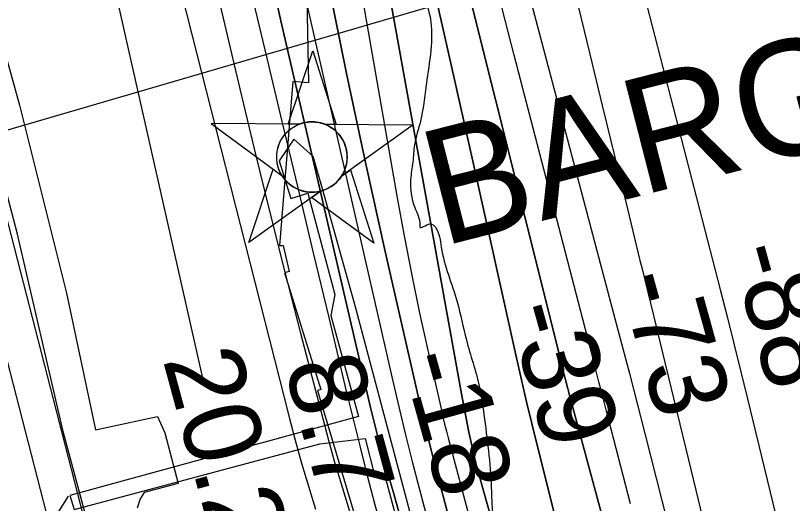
# Model space of a CAD drawing. Extents: x 3405885 to 3443815, y 558517 to 583997.
# Drawn here: x 3413391 to 3414064, y 577623 to 578047 of the extents above; entities that cross this region are included whole.
import ezdxf

# ---------------------------------------------------------------- set-up
doc = ezdxf.new("R2010")
doc.units = 0
for name, color, linetype in [('V-CHAN-DOCK', 7, 'Continuous'), ('V-CHAN-NAID', 7, 'Continuous'), ('V-FLOD-BASE', 7, 'Continuous'), ('V-LEVE-TOET', 7, 'Continuous'), ('V-RIVR-EDGE', 7, 'Continuous'), ('V-RIVR-RANG', 7, 'Continuous'), ('V-ROAD-CNTR', 7, 'Continuous'), ('V-RRAP-RVMT', 7, 'Continuous'), ('V-SURV-LINE', 7, 'Continuous'), ('V-TOPO-DPTH', 7, 'Continuous'), ('V-TOPO-MAJR', 7, 'Continuous'), ('V-TOPO-MINR', 7, 'Continuous'), ('V-TOPO-WATR', 7, 'Continuous')]:
    doc.layers.add(name, color=color, linetype=linetype)

msp = doc.modelspace()

# ---------------------------------------------------------------- linework, layer by layer
at = {"layer": 'V-CHAN-DOCK'}
msp.add_lwpolyline([(3413804.16, 577347.39), (3413685.89, 577792.59), (3413657.04, 577896.35), (3413649.1, 577924.35), (3413632.42, 577939.2), (3413619.6, 577920.48), (3413629.55, 577887.89), (3413644.28, 577892.42), (3413667.68, 577804.44), (3413664.27, 577786.46), (3413688.41, 577698.83), (3413438.09, 577630.26), (3413441.93, 577618.08), (3413654.91, 577675.12), (3413694.17, 577679.57), (3413702.58, 577646.57), (3413710.83, 577648.47), (3413752.94, 577490.9)], dxfattribs=at)
at = {"layer": 'V-CHAN-NAID'}
for points in [[(3413637.08, 577952.36), (3413627.49, 577952.43), (3413648.62, 578015.92), (3413668.84, 577952.14), (3413659.25, 577952.21), (3413657.68, 577952.79), (3413655.58, 577953.41), (3413653.54, 577953.86), (3413651.51, 577954.16), (3413650.34, 577954.28), (3413648.81, 577954.36), (3413647.08, 577954.36), (3413645.71, 577954.29), (3413643.81, 577954.09), (3413642.44, 577953.87), (3413640.66, 577953.48), (3413639.13, 577953.06), (3413638.1, 577952.73)], [(3413637.08, 577952.36), (3413560.59, 577952.91), (3413622.15, 577907.51), (3413621.04, 577909.42), (3413620.23, 577911.04), (3413619.4, 577913.01), (3413618.71, 577915.07), (3413618.34, 577916.39), (3413617.98, 577918.02), (3413617.74, 577919.46), (3413617.55, 577921.06), (3413617.44, 577922.79), (3413617.43, 577924.38), (3413617.54, 577926.45), (3413617.72, 577928.07), (3413618.11, 577930.27), (3413618.59, 577932.19), (3413619.2, 577934.08), (3413619.85, 577935.76), (3413620.58, 577937.35), (3413621.39, 577938.88), (3413622.45, 577940.62), (3413623.48, 577942.09), (3413624.48, 577943.36), (3413625.48, 577944.5), (3413626.79, 577945.84), (3413627.85, 577946.81), (3413629.56, 577948.2), (3413630.77, 577949.07), (3413632.46, 577950.14), (3413634.19, 577951.09), (3413635.64, 577951.77)], [(3413659.25, 577952.21), (3413735.75, 577951.66), (3413673.54, 577907.14), (3413674.45, 577908.63), (3413675.43, 577910.48), (3413676.15, 577912.06), (3413676.89, 577914.02), (3413677.43, 577915.8), (3413677.83, 577917.44), (3413678.19, 577919.45), (3413678.38, 577921.03), (3413678.5, 577923.23), (3413678.47, 577925.29), (3413678.28, 577927.51), (3413678.02, 577929.27), (3413677.52, 577931.5), (3413676.89, 577933.64), (3413676.14, 577935.63), (3413675.49, 577937.07), (3413674.48, 577938.98), (3413673.42, 577940.71), (3413672.2, 577942.41), (3413670.94, 577943.95), (3413669.67, 577945.31), (3413668.04, 577946.85), (3413666.3, 577948.26), (3413664.61, 577949.43), (3413662.73, 577950.57), (3413661.25, 577951.33)], [(3413655.51, 577894.24), (3413593.31, 577849.71), (3413614.44, 577913.2), (3413622.15, 577907.51), (3413622.79, 577906.54), (3413624.17, 577904.68), (3413625.38, 577903.27), (3413626.85, 577901.77), (3413628.24, 577900.51), (3413629.69, 577899.36), (3413631.1, 577898.37), (3413632.77, 577897.34), (3413634.49, 577896.42), (3413636.28, 577895.61), (3413637.72, 577895.06), (3413639.35, 577894.53), (3413641.58, 577893.96), (3413643.11, 577893.68), (3413645.14, 577893.42), (3413646.67, 577893.32), (3413648.53, 577893.29), (3413650.22, 577893.37), (3413651.93, 577893.55), (3413653.83, 577893.86)], [(3413673.54, 577907.14), (3413681.34, 577912.72), (3413701.56, 577848.95), (3413647.71, 577888.66), (3413655.51, 577894.24), (3413657.18, 577894.71), (3413658.79, 577895.27), (3413660.95, 577896.19), (3413662.68, 577897.07), (3413664.55, 577898.18), (3413666.29, 577899.4), (3413667.84, 577900.64), (3413669.13, 577901.81), (3413670.51, 577903.23), (3413671.71, 577904.63), (3413672.83, 577906.1)]]:
    msp.add_lwpolyline(points, close=True, dxfattribs=at)
msp.add_circle((3413647.96, 577923.83), 30.54, dxfattribs=at)
at = {"layer": 'V-FLOD-BASE'}
msp.add_lwpolyline([(3413465.79, 577560.69), (3413432.41, 577685.66), (3413392.86, 577856.9), (3413362.37, 577972.07), (3413330.74, 578093.73), (3413297.96, 578218.34), (3413261.73, 578356.54), (3413239.29, 578440.41), (3413213.87, 578520.76), (3413187.54, 578640.5), (3413147.23, 578803.6), (3413108.08, 578947.71), (3413061.52, 579129.02), (3413012.59, 579309.16), (3412974.93, 579462.82), (3412927.79, 579646.49), (3412885.86, 579814.79), (3412853.92, 579977.72), (3412809.19, 580169.04), (3412768.3, 580316.11)], dxfattribs=at)
at = {"layer": 'V-LEVE-TOET'}
msp.add_lwpolyline([(3413370.35, 578055.62), (3413394.54, 577968.79), (3413435.33, 577805.8), (3413460.48, 577687.13), (3413471.11, 577689.42), (3413514.21, 577698.57), (3413520.6, 577684.38), (3413532.11, 577640.67), (3413502.58, 577632.61), (3413499, 577627.33), (3413496.59, 577619.09)], dxfattribs=at)
at = {"layer": 'V-RIVR-EDGE'}
msp.add_spline([(3412820.89, 582098.27), (3412817.84, 582058.01), (3412815.57, 582029.5), (3412817.71, 582007.93), (3412825.69, 581980.13), (3412850.3, 581879.91), (3412863.71, 581832.72), (3412872.03, 581799.07), (3412892.31, 581722.25), (3412903.17, 581678.36), (3412909.64, 581634.84), (3412920.52, 581598.99), (3412933.97, 581569.35), (3412943.42, 581548.49), (3412954.66, 581511.18), (3412955.33, 581484.86), (3412959.66, 581464.01), (3412965.14, 581459.61), (3412977.89, 581444.95), (3412992.43, 581409.09), (3413006.55, 581353.13), (3413015.19, 581302.3), (3413018.74, 581260.25), (3413013.93, 581236.14), (3413008.78, 581220.07), (3413005.09, 581206.55), (3413003.59, 581194.49), (3413004.66, 581180.23), (3413009.33, 581149.15), (3413020.58, 581117.32), (3413042.04, 581073.03), (3413073.01, 581031.28), (3413081.02, 581018.1), (3413088.65, 580999.81), (3413094.45, 580977.86), (3413100.2, 580939.1), (3413102.69, 580912.04), (3413106.3, 580894.12), (3413113.53, 580861.93), (3413124.77, 580824.25), (3413140.02, 580781.45), (3413146.54, 580756.94), (3413148.69, 580740.12), (3413153.76, 580721.83), (3413161, 580692.57), (3413184.21, 580615.75), (3413193.99, 580582.46), (3413204.19, 580568.17), (3413207.83, 580561.59), (3413213.98, 580535.25), (3413232.08, 580461.73), (3413243.98, 580397.73), (3413252.99, 580345.07), (3413251.86, 580330.82), (3413256.43, 580258.43), (3413262.55, 580217.47), (3413264.64, 580175.43), (3413271.51, 580146.53), (3413278.75, 580117.27), (3413280.18, 580104.84), (3413276.41, 580060.61), (3413276.33, 580025.89), (3413275.56, 580012.36), (3413275.55, 580006.15), (3413277.73, 580003.22), (3413287.96, 580000.64), (3413298.56, 579998.42), (3413303.66, 579992.19), (3413305.47, 579985.24), (3413310.15, 579953.79), (3413314.48, 579931.12), (3413321.02, 579914.65), (3413327.18, 579894.53), (3413327.12, 579868.94), (3413323.4, 579842.63), (3413317.9, 579835.33), (3413316.04, 579824.74), (3413315.63, 579806.46), (3413319.95, 579780.13), (3413327.96, 579765.12), (3413335.62, 579758.16), (3413338.16, 579753.4), (3413338.88, 579747.55), (3413338.87, 579742.8), (3413335.55, 579730.74), (3413330.78, 579723.08), (3413327.83, 579714.31), (3413325.24, 579701.16), (3413326.67, 579689.46), (3413332.12, 579675.92), (3413338.32, 579668.23), (3413342.7, 579666.39), (3413352.57, 579666.73), (3413357.32, 579663.43), (3413365.33, 579652.44), (3413371.87, 579635.24), (3413374.75, 579618.42), (3413377.61, 579592.46), (3413379.35, 579557.36), (3413373.78, 579521.55), (3413375.19, 579501.08), (3413382.08, 579476.94), (3413395.15, 579439.98), (3413408.57, 579400.84), (3413417.61, 579358.78), (3413445.24, 579297.66), (3413449.93, 579271.7), (3413449.83, 579233.31), (3413439.49, 579191.3), (3413438.74, 579182.16), (3413439.81, 579172.66), (3413446, 579161.68), (3413464.94, 579134.58), (3413487.52, 579101.62), (3413496.96, 579074.91), (3413502.74, 579046.39), (3413506.69, 579018.23), (3413510.64, 578990.8), (3413518.59, 578952.4), (3413529.8, 578903.76), (3413538.13, 578871.57), (3413547.91, 578834.62), (3413558.39, 578787.44), (3413566.69, 578743.19), (3413574.63, 578699.3), (3413585.07, 578637.13), (3413595.16, 578577.16), (3413599.47, 578547.54), (3413610.73, 578516.07), (3413620.2, 578503.99), (3413626.04, 578499.22), (3413635.54, 578497.01), (3413635.9, 578494.45), (3413634.06, 578490.06), (3413632.22, 578487.14), (3413632.2, 578479.47), (3413633.24, 578454.97), (3413642.22, 578390.98), (3413644.34, 578359.17), (3413649.04, 578338.69), (3413656.31, 578322.22), (3413667.62, 578313.79), (3413676.01, 578309.01), (3413684.41, 578305.34), (3413688.79, 578300.21), (3413697.9, 578288.49), (3413702.24, 578272.39), (3413709.14, 578250.81), (3413714.94, 578233.25), (3413728.72, 578187.15), (3413734.84, 578151.32), (3413738.77, 578114.39), (3413740.53, 578084.04), (3413746.68, 578059.17), (3413750.66, 578043.44), (3413751.33, 578020.04), (3413747.61, 577990.81), (3413742.03, 577955), (3413736.87, 577934.54), (3413735.37, 577919.56), (3413733.5, 577904.21), (3413737.1, 577880.07), (3413741.45, 577864.71), (3413741.44, 577863.25), (3413750.22, 577865.78), (3413754.97, 577862.85), (3413760.04, 577845.65), (3413773.82, 577798.1), (3413781.78, 577765.18), (3413793.01, 577724.94), (3413796.97, 577700.44), (3413803.39, 577637.18), (3413804.43, 577613.79), (3413807.67, 577591.85), (3413815.27, 577561.12), (3413829.43, 577524.9), (3413841.79, 577493.79), (3413853.78, 577465.98), (3413863.23, 577445.49), (3413869.78, 577431.22), (3413869.77, 577426.1), (3413869.73, 577412.94), (3413868.94, 577389.55), (3413869.22, 577352.99), (3413871.01, 577339.83), (3413873.91, 577328.49), (3413883, 577306.53), (3413889.53, 577287.87), (3413905.14, 577244.33), (3413913.47, 577211.05), (3413925.41, 577161.3), (3413947.56, 577101.66), (3413958.82, 577073.49), (3413969.01, 577057.38), (3413973, 577043.85), (3413979.88, 577014.58), (3414001.97, 576930.82), (3414004.47, 576907.42), (3414006.27, 576897.18), (3414015, 576880.34), (3414024.45, 576858.75), (3414031.34, 576835.7), (3414040.76, 576799.49), (3414054.16, 576750.11), (3414062.48, 576713.9), (3414069.34, 576679.89), (3414074.43, 576668.54), (3414075.15, 576663.42), (3414103.1, 576586.22), (3414107.44, 576564.64), (3414115.39, 576529.17), (3414118.99, 576507.96), (3414142.2, 576433.69), (3414153.45, 576399.3), (3414159.61, 576378.45), (3414164.66, 576348.83), (3414174.05, 576303.84), (3414178, 576274.95), (3414184.15, 576248.25), (3414191.06, 576233.98), (3414204.14, 576202.15), (3414212.13, 576179.46), (3414242.98, 576089.46), (3414264.75, 576025.44), (3414269.45, 576005.68), (3414269.43, 575994.35), (3414267.65, 575989.11)], degree=3, dxfattribs=at)
at = {"layer": 'V-RIVR-RANG'}
msp.add_line((3413350.42, 577937.51), (3414271.79, 578207.11), dxfattribs=at)
at = {"layer": 'V-ROAD-CNTR'}
msp.add_lwpolyline([(3413369.52, 577417.43), (3413386.72, 577444.84), (3413397.69, 577474.18), (3413405.24, 577506.72), (3413414.41, 577551.1), (3413419.38, 577589.88), (3413423.67, 577608.37), (3413436.93, 577629.7)], dxfattribs=at)
at = {"layer": 'V-RRAP-RVMT'}
for points in [[(3413778.5, 578378.05), (3413583.13, 578323.9), (3413613.1, 578215.7), (3413608.4, 578214.45), (3413640.42, 578096.21), (3413641.17, 578096.42), (3413650.98, 578062.07), (3413643.48, 578061.68), (3413645.07, 577988.33), (3413631.51, 577989.47), (3413619.77, 577847.16), (3413623.01, 577846.98), (3413628.35, 577824.52), (3413624.27, 577823.25)], [(3413624.27, 577823.25), (3413655.82, 577722.2), (3413652.79, 577721.39), (3413689.98, 577595.91)]]:
    msp.add_lwpolyline(points, dxfattribs=at)
at = {"layer": 'V-SURV-LINE'}
for points in [[(3412864.61, 579889.25), (3413603.11, 577015.14)], [(3413574.05, 577007.68), (3412835.55, 579881.79)]]:
    msp.add_lwpolyline(points, dxfattribs=at)
at = {"layer": 'V-TOPO-DPTH'}
for points in [[(3413113.8, 580487.79), (3413186.95, 580114.69), (3413203.74, 580017.58), (3413234.81, 579842.97), (3413255.79, 579718.61), (3413318.06, 579422.16), (3413354.3, 579273.08), (3413358.52, 579257.74), (3413360.2, 579247.52), (3413367.73, 579194.71), (3413376.93, 579127.43), (3413384.52, 579097.61), (3413411.48, 578982.6), (3413448.52, 578813.93), (3413532.73, 578434.84), (3413535.26, 578425.47), (3413536.94, 578418.66), (3413621.15, 578042.12), (3413698.65, 577706.48), (3413704.56, 577683.47), (3413708.77, 577666.43), (3413718.9, 577631.5), (3413770.38, 577445.77)], [(3413770.38, 577445.77), (3413718.9, 577631.5), (3413708.77, 577666.43), (3413704.56, 577683.47), (3413698.65, 577706.48), (3413621.15, 578042.12), (3413536.94, 578418.66), (3413535.26, 578425.47), (3413532.73, 578434.84), (3413448.52, 578813.93), (3413411.48, 578982.6), (3413384.52, 579097.61), (3413376.93, 579127.43), (3413367.73, 579194.71), (3413360.2, 579247.52), (3413358.52, 579257.74), (3413354.3, 579273.08), (3413318.06, 579422.16), (3413255.79, 579718.61), (3413234.81, 579842.97), (3413203.74, 580017.58), (3413186.95, 580114.69), (3413113.8, 580487.79)], [(3413900.62, 577444.28), (3413843.18, 577673.73), (3413838.53, 577692.63), (3413833.98, 577711.56), (3413829.58, 577730.53), (3413825.29, 577749.52), (3413786.81, 577922.91), (3413766.68, 578012.74), (3413746.31, 578102.52), (3413725.59, 578192.22), (3413704.63, 578281.86), (3413669.44, 578431.01), (3413665.86, 578446.03), (3413662.26, 578461.04), (3413658.6, 578476.03), (3413654.91, 578491.02), (3413521.89, 579026.6)], [(3413900.62, 577444.28), (3413843.18, 577673.73), (3413838.53, 577692.63), (3413833.98, 577711.56), (3413829.58, 577730.53), (3413825.29, 577749.52), (3413786.81, 577922.91), (3413766.68, 578012.74), (3413746.31, 578102.52), (3413725.59, 578192.22), (3413704.63, 578281.86), (3413669.44, 578431.01), (3413665.86, 578446.03), (3413662.26, 578461.04), (3413658.6, 578476.03), (3413654.91, 578491.02), (3413521.89, 579026.6)], [(3413502.85, 578835.61), (3413521.71, 578756.58), (3413539.89, 578677.39), (3413557.63, 578598.11), (3413580.09, 578495.71), (3413586.14, 578467.52), (3413592.04, 578439.29), (3413597.7, 578411.01), (3413603.2, 578382.7), (3413647.12, 578151.37), (3413662.27, 578073.78), (3413677.97, 577996.3), (3413694.49, 577918.99), (3413711.55, 577841.8), (3413740, 577716.24), (3413743.32, 577701.93), (3413746.74, 577687.64), (3413750.32, 577673.38), (3413754, 577659.15), (3413869.16, 577223.06)], [(3413869.16, 577223.06), (3413754, 577659.15), (3413750.32, 577673.38), (3413746.74, 577687.64), (3413743.32, 577701.93), (3413740, 577716.24), (3413711.55, 577841.8), (3413694.49, 577918.99), (3413677.97, 577996.3), (3413662.27, 578073.78), (3413647.12, 578151.37), (3413603.2, 578382.7), (3413597.7, 578411.01), (3413592.04, 578439.29), (3413586.14, 578467.52), (3413580.09, 578495.71), (3413557.63, 578598.11), (3413539.89, 578677.39), (3413521.71, 578756.58), (3413502.85, 578835.61)], [(3413392.88, 578822.3), (3413416.16, 578718.3), (3413439.37, 578614.3), (3413473.94, 578459.05), (3413479.87, 578432.67), (3413485.86, 578406.3), (3413491.95, 578379.95), (3413498.1, 578353.62), (3413585.45, 577982.92), (3413598.17, 577929.84), (3413611.13, 577876.82), (3413624.48, 577823.9), (3413638.09, 577771.04), (3413662.35, 577678.17), (3413664.05, 577671.8), (3413665.8, 577665.45), (3413667.63, 577659.11), (3413669.51, 577652.79), (3413721.26, 577482.22)], [(3413995.31, 576927.64), (3413796.52, 577634.13), (3413793.68, 577644.55), (3413790.96, 577655.01), (3413788.42, 577665.51), (3413786.01, 577676.03), (3413783.74, 577686.6), (3413781.55, 577697.18), (3413779.5, 577707.78), (3413777.52, 577718.4), (3413668.97, 578321.3), (3413664.81, 578343.58), (3413660.44, 578365.83), (3413655.78, 578388.02), (3413650.92, 578410.17), (3413642.76, 578446.19), (3413641.81, 578450.3), (3413640.85, 578454.39), (3413639.86, 578458.48), (3413638.85, 578462.57), (3413571.86, 578728.8), (3413548.77, 578820.35)], [(3413548.77, 578820.35), (3413571.86, 578728.8), (3413638.85, 578462.57), (3413639.86, 578458.48), (3413640.85, 578454.39), (3413641.81, 578450.3), (3413642.76, 578446.19), (3413650.92, 578410.17), (3413655.78, 578388.02), (3413660.44, 578365.83), (3413664.81, 578343.58), (3413668.97, 578321.3), (3413777.52, 577718.4), (3413779.5, 577707.78), (3413781.55, 577697.18), (3413783.74, 577686.6), (3413786.01, 577676.03), (3413788.42, 577665.51), (3413790.96, 577655.01), (3413793.68, 577644.55), (3413796.52, 577634.13), (3413995.31, 576927.64)], [(3413600.24, 578806.18), (3413624.1, 578709.01), (3413672.49, 578513.08), (3413678.11, 578490.39), (3413683.74, 578467.69), (3413689.38, 578445), (3413695.03, 578422.31), (3413863.31, 577748.33), (3413864.43, 577743.85), (3413865.55, 577739.37), (3413866.69, 577734.9), (3413867.83, 577730.42), (3413869.81, 577722.66), (3413869.96, 577722.07), (3413870.27, 577720.89), (3413870.42, 577720.31), (3413910.72, 577570.71)], [(3413600.24, 578806.18), (3413624.1, 578709.01), (3413672.49, 578513.08), (3413678.11, 578490.39), (3413683.74, 578467.69), (3413689.38, 578445), (3413695.03, 578422.31), (3413863.31, 577748.33), (3413864.43, 577743.85), (3413865.55, 577739.37), (3413866.69, 577734.9), (3413867.83, 577730.42), (3413869.81, 577722.66), (3413869.96, 577722.07), (3413870.27, 577720.89), (3413870.42, 577720.31), (3413910.72, 577570.71)]]:
    msp.add_lwpolyline(points, dxfattribs=at)
at = {"layer": 'V-TOPO-MAJR'}
msp.add_lwpolyline([(3413924.19, 577622.84), (3413903.37, 577703.22), (3413900.06, 577716), (3413896.74, 577728.78), (3413893.43, 577741.56), (3413890.12, 577754.34), (3413847.16, 577919.95), (3413823.27, 578012.29), (3413799.46, 578104.65), (3413775.76, 578197.04), (3413752.13, 578289.44), (3413711.04, 578450.56), (3413708.03, 578462.43), (3413705.04, 578474.3), (3413702.08, 578486.18), (3413699.15, 578498.06), (3413677.34, 578586.88), (3413663.58, 578643.2), (3413649.9, 578699.53), (3413636.35, 578755.9), (3413622.88, 578812.28)], dxfattribs=at)
at = {"layer": 'V-TOPO-MINR'}
for points in [[(3413081.86, 579844.73), (3413248.45, 579225.18), (3413248.61, 579224.57), (3413248.77, 579223.95), (3413249.31, 579221.71), (3413249.98, 579218.85), (3413250.28, 579217.41), (3413250.58, 579215.97), (3413252.06, 579208.54), (3413253.06, 579203.38), (3413254.04, 579198.21), (3413254.98, 579193.04), (3413255.89, 579187.86), (3413324.1, 578790.99), (3413336.33, 578722.49), (3413349.15, 578654.1), (3413362.87, 578585.88), (3413377.17, 578517.78), (3413398.87, 578417.73), (3413402.79, 578399.75), (3413406.75, 578381.77), (3413410.74, 578363.79), (3413414.77, 578345.83), (3413553.94, 577728.17)], [(3413531.79, 579300.44), (3413719, 578510.94), (3413720.19, 578505.93), (3413721.39, 578500.92), (3413722.6, 578495.91), (3413723.82, 578490.9), (3413725.74, 578483.03), (3413726.27, 578480.89), (3413726.82, 578478.75), (3413730.32, 578465.24), (3413732.36, 578457.41), (3413734.4, 578449.59), (3413736.45, 578441.77), (3413738.52, 578433.95), (3413909.44, 577788.1), (3413916.29, 577762.06), (3413923.09, 577736.01), (3413929.81, 577709.94), (3413936.48, 577683.85), (3413976.17, 577527.67)], [(3413420.98, 579246.53), (3413600.24, 578552.02), (3413604.55, 578534.96), (3413608.74, 578517.88), (3413612.76, 578500.76), (3413616.67, 578483.6), (3413620.37, 578466.41), (3413623.91, 578449.18), (3413627.21, 578431.9), (3413630.34, 578414.59), (3413721.85, 577888.35), (3413727.83, 577855.46), (3413734.14, 577822.64), (3413740.95, 577789.92), (3413748.09, 577757.27), (3413760.12, 577704.17), (3413761.53, 577698.13), (3413762.98, 577692.09), (3413764.49, 577686.07), (3413766.05, 577680.07), (3413946.44, 577000.4)], [(3413332.16, 579232.25), (3413442.49, 578726.4), (3413453.9, 578674.36), (3413465.38, 578622.34), (3413476.96, 578570.35), (3413488.62, 578518.37), (3413506.22, 578440.28), (3413509.16, 578427.36), (3413512.13, 578414.45), (3413515.15, 578401.56), (3413518.21, 578388.67), (3413608.76, 578009.73), (3413622.21, 577953.43), (3413635.65, 577897.12), (3413649.07, 577840.82), (3413662.49, 577784.51), (3413677.66, 577720.78), (3413683.58, 577696.36), (3413689.63, 577671.97), (3413695.87, 577647.64), (3413702.25, 577623.33), (3413708.8, 577599.07)], [(3413521.89, 579026.6), (3413654.91, 578491.02), (3413658.6, 578476.03), (3413662.26, 578461.04), (3413665.86, 578446.03), (3413669.44, 578431.01), (3413704.63, 578281.86), (3413725.59, 578192.22), (3413746.31, 578102.52), (3413766.68, 578012.74), (3413786.81, 577922.91), (3413825.29, 577749.52), (3413829.58, 577730.53), (3413833.98, 577711.56), (3413838.53, 577692.63), (3413843.18, 577673.73), (3413900.62, 577444.28)], [(3413344.07, 578915.66), (3413440.37, 578469.07), (3413448.15, 578433.05), (3413455.97, 578397.03), (3413463.81, 578361.03), (3413471.69, 578325.03), (3413479.76, 578289.08), (3413488.06, 578253.18), (3413496.71, 578217.36), (3413505.59, 578181.6), (3413628.19, 577698.15), (3413633.47, 577678.09), (3413638.98, 577658.1), (3413644.86, 577638.21), (3413650.98, 577618.4)], [(3413502.85, 578835.61), (3413521.71, 578756.58), (3413539.89, 578677.39), (3413557.63, 578598.11), (3413580.09, 578495.71), (3413586.14, 578467.52), (3413592.04, 578439.29), (3413597.7, 578411.01), (3413603.2, 578382.7), (3413647.12, 578151.37), (3413662.27, 578073.78), (3413677.97, 577996.3), (3413694.49, 577918.99), (3413711.55, 577841.8), (3413740, 577716.24), (3413743.32, 577701.93), (3413746.74, 577687.64), (3413750.32, 577673.38), (3413754, 577659.15), (3413869.16, 577223.06)], [(3413392.88, 578822.3), (3413416.16, 578718.3), (3413439.37, 578614.3), (3413473.94, 578459.05), (3413479.87, 578432.67), (3413485.86, 578406.3), (3413491.95, 578379.95), (3413498.1, 578353.62), (3413585.45, 577982.92), (3413598.17, 577929.84), (3413611.13, 577876.82), (3413624.48, 577823.9), (3413638.09, 577771.04), (3413662.35, 577678.17), (3413664.05, 577671.8), (3413665.8, 577665.45), (3413667.63, 577659.11), (3413669.51, 577652.79), (3413721.26, 577482.22)], [(3413478.88, 578819.96), (3413557.76, 578457.29), (3413560.66, 578443.85), (3413563.53, 578430.41), (3413566.35, 578416.96), (3413569.14, 578403.5), (3413588.14, 578311.08), (3413600.59, 578251.45), (3413613.31, 578191.88), (3413626.4, 578132.39), (3413639.75, 578072.95), (3413718.1, 577729.32), (3413723.53, 577706.04), (3413729.12, 577682.8), (3413734.93, 577659.62), (3413740.91, 577636.47), (3413788.54, 577455.56)], [(3413548.77, 578820.35), (3413571.86, 578728.8), (3413638.85, 578462.57), (3413639.86, 578458.48), (3413640.85, 578454.39), (3413641.81, 578450.3), (3413642.76, 578446.19), (3413650.92, 578410.17), (3413655.78, 578388.02), (3413660.44, 578365.83), (3413664.81, 578343.58), (3413668.97, 578321.3), (3413777.52, 577718.4), (3413779.5, 577707.78), (3413781.55, 577697.18), (3413783.74, 577686.6), (3413786.01, 577676.03), (3413788.42, 577665.51), (3413790.96, 577655.01), (3413793.68, 577644.55), (3413796.52, 577634.13), (3413995.31, 576927.64)], [(3413910.72, 577570.71), (3413870.42, 577720.31), (3413870.27, 577720.89), (3413869.96, 577722.07), (3413869.81, 577722.66), (3413867.83, 577730.42), (3413866.69, 577734.9), (3413865.55, 577739.37), (3413864.43, 577743.85), (3413863.31, 577748.33), (3413695.03, 578422.31), (3413689.38, 578445), (3413683.74, 578467.69), (3413678.11, 578490.39), (3413672.49, 578513.08), (3413624.1, 578709.01), (3413600.24, 578806.18)], [(3413708.77, 578792.97), (3413729.07, 578693.52), (3413760.33, 578548.31), (3413766.17, 578521.69), (3413772.15, 578495.09), (3413778.34, 578468.55), (3413784.67, 578442.03), (3413888.74, 578013.19), (3413899.61, 577968.41), (3413910.49, 577923.62), (3413921.38, 577878.84), (3413932.28, 577834.06), (3413933.77, 577827.93), (3413943.92, 577786.22), (3413954.05, 577744.5), (3413964.16, 577702.78), (3413974.26, 577661.06), (3414073.2, 577251.94)], [(3413838.28, 578443.06), (3414002.16, 577807.66), (3414008.13, 577784.31), (3414014.01, 577760.95), (3414019.79, 577737.55), (3414025.49, 577714.14), (3414056.81, 577584.18)]]:
    msp.add_lwpolyline(points, dxfattribs=at)
at = {"layer": 'V-TOPO-WATR'}
msp.add_lwpolyline([(3413770.38, 577445.77), (3413718.9, 577631.5), (3413708.77, 577666.43), (3413704.56, 577683.47), (3413698.65, 577706.48), (3413621.15, 578042.12), (3413536.94, 578418.66), (3413535.26, 578425.47), (3413532.73, 578434.84), (3413448.52, 578813.93), (3413411.48, 578982.6), (3413384.52, 579097.61), (3413376.93, 579127.43), (3413367.73, 579194.71), (3413360.2, 579247.52), (3413358.52, 579257.74), (3413354.3, 579273.08), (3413318.06, 579422.16), (3413255.79, 579718.61), (3413234.81, 579842.97), (3413203.74, 580017.58), (3413186.95, 580114.69), (3413113.8, 580487.79)], dxfattribs=at)

# ---------------------------------------------------------------- texts
at = {"layer": 'V-CHAN-NAID'}
msp.add_text(' BARGE DOCK (166.7)', height=100, rotation=14.33518, dxfattribs=at).set_placement((3413724.49, 577836.88))
at = {"layer": 'V-RIVR-RANG'}
for s, rotation, p in [('-88', 285.47722, (3414010.55, 577842.78)), ('-73', 285.47722, (3413913.55, 577818.37)), ('-39', 285.47722, (3413817.18, 577791.66)), ('20.2', 285.19833, (3413518.52, 577748.22)), ('8.7', 285.19833, (3413623.67, 577742.6)), ('-18', 285.47722, (3413725.17, 577749.2))]:
    msp.add_text(s, height=67, rotation=rotation, dxfattribs=at).set_placement(p)

doc.saveas('drawing.dxf')
